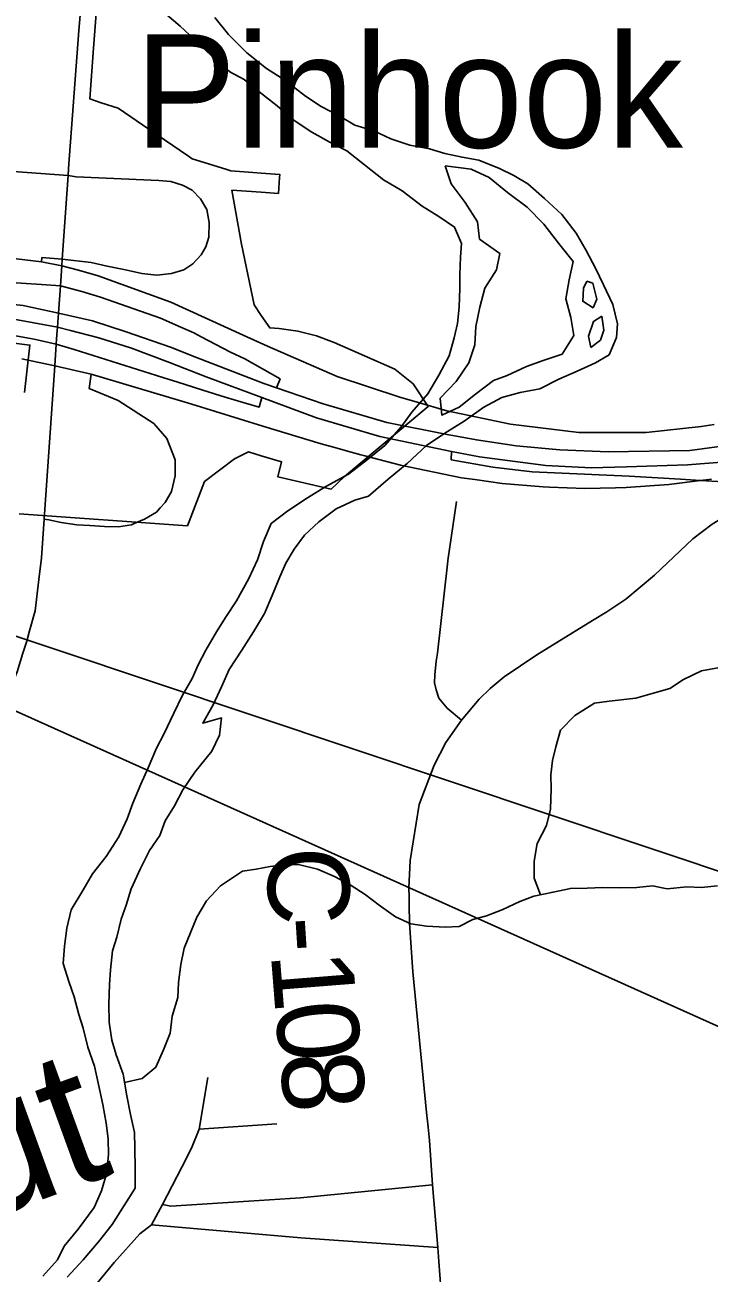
# Model space of a CAD drawing. Extents: x 0 to 34, y 0 to 22.
# Drawn here: x 6.673 to 7.149, y 17.262 to 18.131 of the extents above; entities that cross this region are included whole.
import ezdxf

# ---------------------------------------------------------------- set-up
doc = ezdxf.new("R2010")
doc.units = 0
for name, color, linetype in [('GM_X_City_Street', 7, 'Continuous'), ('GM_X_Corporation', 7, 'Continuous'), ('GM_X_County_Road', 7, 'Continuous'), ('GM_X_County_Road_Text', 7, 'Continuous'), ('GM_X_Interchange_Ramps', 7, 'Continuous'), ('GM_X_Major_River', 7, 'Continuous'), ('GM_X_Major_River_Text', 7, 'Continuous'), ('GM_X_Minor_River', 7, 'Continuous'), ('GM_X_State_Route', 7, 'Continuous'), ('GM_X_Township_Road', 7, 'Continuous'), ('GM_X_Unincorporated_Text', 7, 'Continuous'), ('SH_Text', 7, 'Continuous')]:
    doc.layers.add(name, color=color, linetype=linetype)

msp = doc.modelspace()

# ---------------------------------------------------------------- linework, layer by layer
at = {"layer": 'GM_X_City_Street'}
for points in [[(6.97703, 17.64686), (6.967, 17.6552), (6.96137, 17.66207), (6.95934, 17.66793), (6.95832, 17.67289), (6.95843, 17.6784), (6.95945, 17.68798), (6.96023, 17.69357), (6.96723, 17.75536), (6.96753, 17.75805), (6.97365, 17.79917)], [(6.71113, 17.24034), (6.73519, 17.26937)]]:
    msp.add_lwpolyline(points, dxfattribs=at)
at = {"layer": 'GM_X_Corporation'}
for points in [[(6.72493, 18.16895), (6.7208, 18.11481), (6.71811, 18.07951), (6.726, 18.07668), (6.73784, 18.07293), (6.75917, 18.0584), (6.78696, 18.03947), (6.7895, 18.03774), (6.81282, 18.03044), (6.81626, 18.02937), (6.8318, 18.0282), (6.8376, 18.02777), (6.85045, 18.0268), (6.85031, 18.02471), (6.84957, 18.01354), (6.8376, 18.01436), (6.81709, 18.01576), (6.82379, 17.97826), (6.83251, 17.93593), (6.8376, 17.92851), (6.84344, 17.91997), (6.84993, 17.91965), (6.86308, 17.91777), (6.87593, 17.91444), (6.88833, 17.9097), (6.93061, 17.89114), (6.94342, 17.88093), (6.95391, 17.86534), (6.89555, 17.8166), (6.8862, 17.8078), (6.84912, 17.81625), (6.85176, 17.82672), (6.8376, 17.83092), (6.82859, 17.83359), (6.81896, 17.82885), (6.79801, 17.81297), (6.78607, 17.78225), (6.66893, 17.7904)], [(6.67253, 17.87501), (6.67645, 17.90802), (6.50061, 17.93014)]]:
    msp.add_lwpolyline(points, dxfattribs=at)
at = {"layer": 'GM_X_County_Road'}
for p, q in [((6.68625, 17.78681), (6.68696, 17.79692)), ((6.96059, 17.2798), (6.95781, 17.31245)), ((6.96132, 17.26993), (6.96059, 17.2798)), ((6.96494, 17.22059), (6.96132, 17.26993))]:
    msp.add_line(p, q, dxfattribs=at)
for points in [[(6.68696, 17.79692), (6.69374, 17.89363), (6.69474, 17.90859), (6.69527, 17.91537), (6.69562, 17.92042), (6.69631, 17.93021), (6.69763, 17.94915), (6.69862, 17.96322), (6.69895, 17.96788), (6.70303, 18.026), (6.7034, 18.03105), (6.71041, 18.1271), (6.71501, 18.17789), (6.71622, 18.19016)], [(7.06834, 17.71618), (7.07827, 17.72226), (7.09157, 17.73116), (7.11151, 17.74788), (7.13812, 17.77304), (7.15164, 17.7834), (7.16426, 17.79106), (7.18408, 17.79827), (7.22657, 17.8053), (7.25336, 17.80741), (7.28174, 17.80641)], [(6.67446, 17.70268), (6.67605, 17.70901), (6.68006, 17.72297), (6.68267, 17.74477), (6.68452, 17.75997), (6.68625, 17.78681)], [(6.94049, 17.52402), (6.94036, 17.52987), (6.94125, 17.54923), (6.94759, 17.58822), (6.95799, 17.61543), (6.96621, 17.6312), (6.97703, 17.64686), (6.98942, 17.6614), (6.99697, 17.66894), (7.00665, 17.67706), (7.0295, 17.69241), (7.06834, 17.71618)], [(6.1813, 17.18519), (6.37453, 17.36476), (6.5248, 17.51025), (6.59812, 17.58209), (6.62262, 17.60741), (6.63199, 17.61859), (6.64054, 17.62994), (6.64629, 17.63898), (6.65106, 17.6472), (6.6555, 17.65476), (6.66158, 17.66611), (6.6675, 17.68057), (6.67145, 17.69356), (6.67424, 17.70178), (6.67446, 17.70268)], [(6.95269, 17.37362), (6.94303, 17.47162), (6.94087, 17.50552), (6.94061, 17.51818), (6.94049, 17.52402)], [(6.95377, 17.36351), (6.95328, 17.36762), (6.95269, 17.37362)], [(6.95781, 17.31245), (6.95688, 17.32333), (6.95486, 17.35427), (6.95377, 17.36351)]]:
    msp.add_lwpolyline(points, dxfattribs=at)
at = {"layer": 'GM_X_Interchange_Ramps'}
for points in [[(6.70303, 18.026), (6.70865, 18.02513), (6.76611, 18.02259), (6.77467, 18.02177), (6.78263, 18.01933), (6.78936, 18.01586), (6.79527, 18.00974), (6.79976, 18.0024), (6.80139, 17.99342), (6.80098, 17.98322), (6.79895, 17.97629), (6.79568, 17.97078), (6.78997, 17.96466), (6.78365, 17.96038), (6.77508, 17.95773), (6.76488, 17.95671), (6.75448, 17.95773), (6.74306, 17.96038), (6.73021, 17.96283), (6.71899, 17.96548), (6.69895, 17.96788), (6.68479, 17.96887), (6.68455, 17.96606)], [(7.15293, 17.85282), (7.14398, 17.85127), (7.10561, 17.8472), (7.05876, 17.8472), (7.01123, 17.85297), (6.96679, 17.86222), (6.94627, 17.86815), (6.93416, 17.87164), (6.89036, 17.88624), (6.842, 17.90735), (6.82493, 17.9148), (6.77459, 17.93784), (6.72389, 17.9563), (6.71022, 17.96021), (6.69862, 17.96322), (6.68455, 17.96606), (6.66131, 17.96868)], [(6.69763, 17.94915), (6.68442, 17.95014), (6.65627, 17.95199)], [(6.79581, 17.91378), (6.79071, 17.91649), (6.78152, 17.92056), (6.76748, 17.92678), (6.72551, 17.94131), (6.71255, 17.9452), (6.69763, 17.94915)], [(6.61853, 17.92109), (6.6233, 17.9205), (6.62692, 17.92004), (6.64166, 17.91791), (6.65121, 17.91651), (6.66514, 17.9147), (6.67936, 17.91204), (6.69474, 17.90859)], [(6.84825, 17.87815), (6.85068, 17.88446), (6.82602, 17.89834), (6.8162, 17.90296), (6.79581, 17.91378)], [(6.69474, 17.90859), (6.70731, 17.90489), (6.77348, 17.88398), (6.77877, 17.88231)], [(6.67078, 17.89836), (6.69378, 17.89362), (6.71898, 17.8877)], [(6.71898, 17.8877), (6.71778, 17.87776), (6.73786, 17.86943), (6.76279, 17.85333), (6.77184, 17.84296), (6.77757, 17.82818), (6.77757, 17.81693), (6.77515, 17.80611), (6.77058, 17.79851), (6.76723, 17.79477)], [(6.71898, 17.8877), (6.77131, 17.87226), (6.78926, 17.86676), (6.8387, 17.85161), (6.87928, 17.83936), (6.89034, 17.83623), (6.89602, 17.83462), (6.9069, 17.83154), (6.90976, 17.83079)], [(6.77877, 17.88231), (6.79677, 17.87663), (6.81247, 17.87174), (6.82503, 17.86808), (6.83611, 17.86485), (6.83789, 17.87158)], [(6.90976, 17.83079), (6.9346, 17.82429), (6.97706, 17.8156), (6.98628, 17.81432), (7.0054, 17.81168), (7.03391, 17.80926), (7.03844, 17.8091), (7.06289, 17.80821), (7.0844, 17.80872), (7.09185, 17.80889), (7.12137, 17.81095), (7.14356, 17.81378), (7.15112, 17.81473)], [(6.97009, 17.8339), (6.96994, 17.82819), (6.99889, 17.82293), (7.0263, 17.81964), (7.09381, 17.81665), (7.12969, 17.8146), (7.14356, 17.81378), (7.16325, 17.81261), (7.17959, 17.81219), (7.20309, 17.81267), (7.22025, 17.81391), (7.28111, 17.81831), (7.3305, 17.8219), (7.37928, 17.82457), (7.40816, 17.82491), (7.43607, 17.8233), (7.46158, 17.821), (7.49257, 17.81673), (7.51473, 17.81416)], [(6.76723, 17.79477), (6.76455, 17.79177), (6.75617, 17.7867), (6.74914, 17.78378)], [(6.74914, 17.78378), (6.74713, 17.78295), (6.73808, 17.7814), (6.72837, 17.78163), (6.71823, 17.78229), (6.70918, 17.78295), (6.69815, 17.7845), (6.68954, 17.78626), (6.68625, 17.78681)]]:
    msp.add_lwpolyline(points, dxfattribs=at)
at = {"layer": 'GM_X_Major_River'}
for points in [[(6.76706, 18.14186), (6.78104, 18.13002), (6.79123, 18.12048), (6.80407, 18.10828), (6.81578, 18.09835), (6.82561, 18.09299), (6.83581, 18.08459), (6.84866, 18.07466), (6.86037, 18.06436), (6.87285, 18.05633), (6.88495, 18.04944), (6.89706, 18.04331), (6.90953, 18.03338), (6.92275, 18.02307), (6.93561, 18.01541), (6.94959, 18.00472), (6.96131, 17.99745), (6.97228, 17.99019), (6.97715, 17.97877), (6.97635, 17.96929), (6.97591, 17.95714), (6.97586, 17.94765), (6.97542, 17.93436), (6.97422, 17.92298), (6.9719, 17.91312), (6.96843, 17.9006), (6.96115, 17.88697), (6.9535, 17.87409), (6.94244, 17.86124), (6.93518, 17.8514), (6.92374, 17.83816), (6.91155, 17.82835), (6.89822, 17.81816), (6.88263, 17.8095), (6.86969, 17.80158), (6.856, 17.79253), (6.84457, 17.78385), (6.8392, 17.77135), (6.83497, 17.75846), (6.82883, 17.74558), (6.82041, 17.73005), (6.81315, 17.71907), (6.80627, 17.70847), (6.799, 17.69559), (6.79364, 17.68537), (6.78942, 17.6759), (6.78253, 17.66378), (6.77678, 17.65165), (6.76989, 17.63764), (6.76452, 17.62741), (6.75877, 17.61377), (6.75378, 17.6024), (6.74802, 17.58914), (6.74418, 17.57814), (6.73843, 17.56564), (6.72963, 17.55201), (6.72009, 17.53991), (6.71321, 17.52817)], [(6.80534, 18.13598), (6.81477, 18.12417), (6.8276, 18.11158), (6.8412, 18.10051), (6.85406, 18.09248), (6.86842, 18.08141), (6.87938, 18.07414), (6.89187, 18.06763), (6.90283, 18.06112), (6.91609, 18.05726), (6.92782, 18.05152), (6.94108, 18.04728), (6.95472, 18.04456), (6.96533, 18.04148), (6.97745, 18.03876), (6.9892, 18.03681), (7.00358, 18.03105), (7.01342, 18.02607), (7.02326, 18.02033), (7.03496, 18.01002), (7.04705, 17.99896), (7.05684, 17.986), (7.06399, 17.97382), (7.07038, 17.96164), (7.07601, 17.94985), (7.08239, 17.93615), (7.08574, 17.92284), (7.08494, 17.91336), (7.07994, 17.90123), (7.07043, 17.89558), (7.05751, 17.88994), (7.04496, 17.88431), (7.03165, 17.87753), (7.01799, 17.87494), (7.00507, 17.87158), (6.99252, 17.8648), (6.97882, 17.85499), (6.96551, 17.8467), (6.95257, 17.83803), (6.93923, 17.82556), (6.9259, 17.81461), (6.91219, 17.80291), (6.90269, 17.79991), (6.88976, 17.7939), (6.87758, 17.78484), (6.86767, 17.77577), (6.86042, 17.76593), (6.85468, 17.75609)], [(6.96566, 18.03274), (6.96977, 18.02019), (6.97957, 18.00724), (6.98823, 17.99391), (6.98969, 17.98176), (7.00367, 17.97182), (7.00134, 17.96044), (6.99331, 17.94757), (6.98983, 17.9343), (6.98711, 17.92102), (6.98629, 17.90811), (6.98206, 17.8956), (6.97327, 17.88274), (6.96221, 17.87102), (6.96329, 17.85924), (6.97546, 17.86488), (6.98688, 17.87394), (6.99944, 17.88338), (7.00894, 17.88675), (7.02225, 17.89314), (7.03403, 17.89726), (7.04714, 17.9017)], [(7.04714, 17.9017), (7.05536, 17.91463), (7.05314, 17.92717), (7.04979, 17.94009), (7.05213, 17.95337), (7.05485, 17.96627), (7.04467, 17.97884), (7.0345, 17.99218), (7.0228, 18.004), (7.00919, 18.01432), (6.99635, 18.02463), (6.98386, 18.03038), (6.96566, 18.03274)], [(7.06427, 17.95256), (7.06197, 17.94763), (7.06154, 17.93852), (7.06873, 17.93393)], [(7.06873, 17.93393), (7.07141, 17.94), (7.06843, 17.95102), (7.06427, 17.95256)], [(7.07477, 17.92821), (7.06906, 17.92444), (7.06559, 17.91421), (7.06707, 17.90623)], [(7.06707, 17.90623), (7.07393, 17.91151), (7.07624, 17.91833), (7.07477, 17.92821)], [(6.85468, 17.75609), (6.85046, 17.74662), (6.84508, 17.73373), (6.83971, 17.72123), (6.83206, 17.70835), (6.82403, 17.69548), (6.81525, 17.68223), (6.80987, 17.67011), (6.80412, 17.6576), (6.79685, 17.64473), (6.80977, 17.64846), (6.80857, 17.63632), (6.8032, 17.62533), (6.79137, 17.61058), (6.78297, 17.59847), (6.77722, 17.58711), (6.77072, 17.57688), (6.76688, 17.56665), (6.75962, 17.55605), (6.75349, 17.54355), (6.74697, 17.52953), (6.7435, 17.51816), (6.74004, 17.5083), (6.73694, 17.49578), (6.73386, 17.4863), (6.73265, 17.47302), (6.73185, 17.46277), (6.7314, 17.44911), (6.73172, 17.43657), (6.73355, 17.42403), (6.73653, 17.41377), (6.7414, 17.40046), (6.74398, 17.38526), (6.74657, 17.37234), (6.74916, 17.35979), (6.74949, 17.34878), (6.74979, 17.33473), (6.74973, 17.32106), (6.74208, 17.30894), (6.73367, 17.29569), (6.72413, 17.28359), (6.71344, 17.2711), (6.70238, 17.259)], [(6.71321, 17.52817), (6.70517, 17.51491), (6.70208, 17.50202), (6.7005, 17.4895), (6.69968, 17.47735), (6.70341, 17.4648), (6.70715, 17.45415), (6.7105, 17.44199), (6.71349, 17.43248), (6.71684, 17.41918), (6.72132, 17.40587), (6.72429, 17.39332), (6.72726, 17.37926), (6.72947, 17.36634), (6.73093, 17.35532), (6.73126, 17.34431), (6.72967, 17.33102), (6.7262, 17.31927), (6.72121, 17.30752), (6.71014, 17.29238), (6.70022, 17.28066), (6.69562, 17.27119), (6.68532, 17.25984)]]:
    msp.add_lwpolyline(points, dxfattribs=at)
at = {"layer": 'GM_X_Minor_River'}
for points in [[(7.03197, 17.52526), (7.02761, 17.53681), (7.02772, 17.54858), (7.02973, 17.56109), (7.03629, 17.57356), (7.03904, 17.58493), (7.03955, 17.59898), (7.03926, 17.60886), (7.04049, 17.61872), (7.04285, 17.62819), (7.04598, 17.63993), (7.05593, 17.65009), (7.06965, 17.6587), (7.0799, 17.66012), (7.09849, 17.66223), (7.10989, 17.66554), (7.12205, 17.66884), (7.13158, 17.67521), (7.14414, 17.68117), (7.15553, 17.68334)], [(6.74241, 17.3945), (6.75459, 17.39733), (6.76414, 17.40521), (6.76956, 17.41731), (6.77421, 17.42904), (6.77545, 17.4408), (6.77936, 17.45368), (6.77984, 17.46431), (6.78147, 17.47683), (6.78384, 17.4882), (6.7885, 17.49955), (6.79276, 17.50976), (6.79931, 17.52109), (6.80926, 17.53163), (6.82451, 17.54174), (6.834, 17.54318), (6.84387, 17.54498), (6.85335, 17.54603), (6.86359, 17.54632), (6.87683, 17.54316), (6.88853, 17.53811), (6.89947, 17.53231), (6.91001, 17.52537), (6.9198, 17.51807), (6.9311, 17.50999), (6.94167, 17.50495), (6.95264, 17.50333), (6.9659, 17.50283), (6.97538, 17.50312), (6.9849, 17.50797), (6.9944, 17.51054), (7.00581, 17.51498), (7.01761, 17.52057), (7.0275, 17.52428), (7.04079, 17.52719), (7.05294, 17.52974), (7.06469, 17.53001), (7.07531, 17.53029), (7.08782, 17.53017), (7.09919, 17.53044), (7.11019, 17.53148), (7.1204, 17.52948), (7.13406, 17.53088), (7.14391, 17.53041), (7.15529, 17.53144)]]:
    msp.add_lwpolyline(points, dxfattribs=at)
at = {"layer": 'GM_X_State_Route'}
for points in [[(5.91644, 17.99397), (6.01147, 17.98625), (6.08068, 17.9804), (6.08643, 17.98009), (6.10444, 17.97852), (6.11324, 17.97791), (6.16022, 17.97485), (6.19902, 17.97189), (6.5055, 17.94959), (6.54229, 17.94688), (6.59782, 17.94289), (6.63853, 17.93895), (6.67165, 17.93545), (6.69631, 17.93021), (6.72001, 17.92498), (6.74337, 17.91724), (6.77434, 17.9066), (6.79239, 17.89928), (6.83942, 17.88114), (6.84825, 17.87815)], [(6.05303, 17.97368), (6.07237, 17.97196), (6.08581, 17.97076), (6.10397, 17.96954), (6.11244, 17.96899), (6.15493, 17.96622), (6.1809, 17.96445), (6.20389, 17.96297), (6.23289, 17.9607), (6.2903, 17.95656), (6.34998, 17.95202), (6.41646, 17.94728), (6.50485, 17.94024), (6.54203, 17.93742), (6.59752, 17.93281), (6.6302, 17.93018), (6.66266, 17.92645), (6.69562, 17.92042), (6.70459, 17.91814)], [(6.70459, 17.91814), (6.72451, 17.91307), (6.7471, 17.90584), (6.77364, 17.89597), (6.7993, 17.88588), (6.83789, 17.87158), (6.87606, 17.85736), (6.92015, 17.84442), (6.97009, 17.8339)], [(6.84825, 17.87815), (6.88079, 17.86715), (6.92499, 17.8542), (6.96829, 17.84555)], [(6.96829, 17.84555), (6.97112, 17.84498), (6.98738, 17.84203), (7.01514, 17.83793), (7.04561, 17.83499), (7.07912, 17.83362), (7.13617, 17.8347), (7.17717, 17.84026)], [(6.97009, 17.8339), (6.98968, 17.83017), (7.01446, 17.82688), (7.03574, 17.82425), (7.06732, 17.82249), (7.09188, 17.82315), (7.13443, 17.82468), (7.17611, 17.82797), (7.19146, 17.82973), (7.21931, 17.8339), (7.25879, 17.83872), (7.26177, 17.83908)]]:
    msp.add_lwpolyline(points, dxfattribs=at)
at = {"layer": 'GM_X_Township_Road'}
for p, q in [((6.6552, 18.02957), (6.70303, 18.026)), ((6.79435, 17.36216), (6.84852, 17.36586))]:
    msp.add_line(p, q, dxfattribs=at)
for points in [[(6.78226, 17.3357), (6.78905, 17.34877), (6.79435, 17.36216), (6.80035, 17.39816)], [(6.73519, 17.26937), (6.75306, 17.28922), (6.761, 17.29555), (6.76869, 17.30957), (6.78226, 17.3357)], [(6.76869, 17.30957), (6.77449, 17.30852), (6.82898, 17.31192), (6.86492, 17.31422), (6.95688, 17.32333)], [(6.761, 17.29555), (6.86509, 17.28655), (6.96059, 17.2798)]]:
    msp.add_lwpolyline(points, dxfattribs=at)
at = {"layer": 'SH_Text'}
msp.add_lwpolyline([(9.25, 16.84191), (6.20965, 17.85805), (9.25, 16.49411)], close=True, dxfattribs=at)

# ---------------------------------------------------------------- texts
at = {"layer": 'GM_X_County_Road_Text'}
for s, rotation, p in [('C', 270.88994, (6.84175, 17.55854)), ('-', 273.69405, (6.8426, 17.50885)), ('1', 274.53803, (6.84417, 17.48465)), ('0', 275.33477, (6.84701, 17.4489)), ('8', 275.53937, (6.85029, 17.41384))]:
    msp.add_text(s, height=0.05682, rotation=rotation, dxfattribs=at).set_placement(p)
at = {"layer": 'GM_X_Major_River_Text'}
msp.add_text('Walnut', height=0.094701, rotation=20.00453, dxfattribs=at).set_placement((6.36585, 17.19688))
at = {"layer": 'GM_X_Unincorporated_Text'}
msp.add_text('Pinhook', height=0.078977, rotation=0.00001, dxfattribs=at).set_placement((6.74964, 18.0454))

doc.saveas('drawing.dxf')
